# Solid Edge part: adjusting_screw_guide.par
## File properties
Title: Adjusting screw guide
Author: Robert a Rhodes jr
Template: Normal.par
Last saved by: CADCIM
Revision: 15
Application: Solid Edge
Accuracy: 0.99
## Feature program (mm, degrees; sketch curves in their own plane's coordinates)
sketch for "unnamed Protrusion 1" plane through (0, 0, 0) normal (0, -1, 0) x-axis (1, 0, 0)
  circle centre (0, 0) radius 7.9375
extrude "unnamed Protrusion 1" add finite 63.5 along +normal
sketch for "ExtrudedProtrusion_2" plane through (0, -63.5, 0) normal (0, -1, 0) x-axis (1, 0, 0)
  circle centre (0, 0) radius 6.3119
extrude "ExtrudedProtrusion_2" add finite 76.2 along +normal
chamfer "Chamfer_1" setback 1.5748
sketch for "ExtrudedCutout_1" plane through (0, 0, 0) normal (0, 0, 1) x-axis (1, 0, 0)
  line (1.1811, 0) -> (1.1811, -4.7498)
  line (1.1811, -4.7498) -> (-1.1811, -4.7498)
  line (-1.1811, -4.7498) -> (-1.1811, 0)
  line (-1.1811, 0) -> (1.1811, 0)
extrude "ExtrudedCutout_1" cut finite 101.6 symmetric
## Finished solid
Body 1: solid body, 10 faces, 16 edges, 8 vertices.
  Faces by surface: plane 7, cylinder 2, cone 1
  Edges by curve: circle 8, line 8
Bounding box of the edges (mm): 15.875 x 139.700 x 15.875, from (-7.9375, -139.7, -7.9375) to (7.9375, 0, 7.9375).
Cylindrical faces by radius (mm): R6.3119 x1, R7.9375 x1
Conical faces (half-angle, radius in mm at the cone's reference point): 45 deg R6.3119 x1
Planar faces by outward normal: +x 1, +y 3, -x 1, -y 2
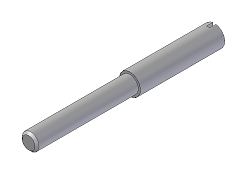
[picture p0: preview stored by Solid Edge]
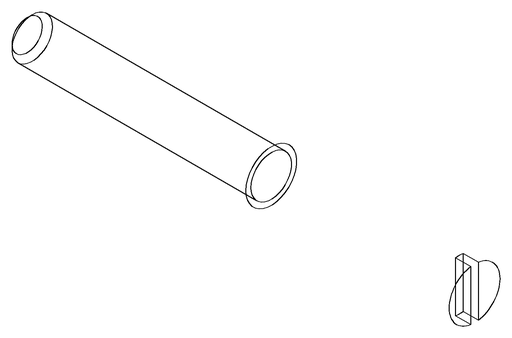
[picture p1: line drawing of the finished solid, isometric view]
